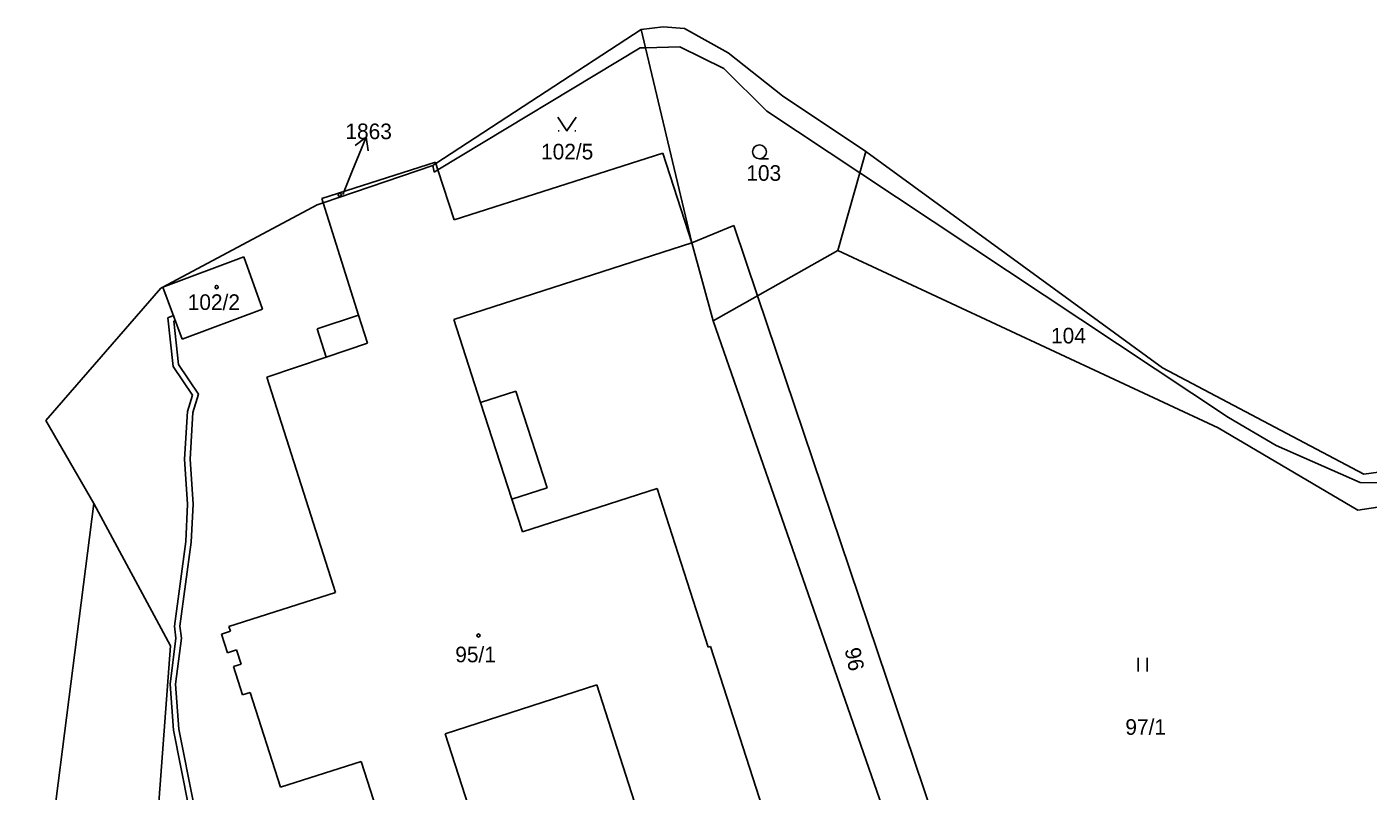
# Model space of a CAD drawing. Extents: x -670359 to -660124, y -978807 to -970072.
# Drawn here: x -670303.1 to -670157, y -977284.7 to -977201.4 of the extents above; entities that cross this region are included whole.
import ezdxf

# ---------------------------------------------------------------- set-up
doc = ezdxf.new("R2010")
doc.units = 0
for name, color, linetype in [('Hranice kat_území', 7, 'Continuous'), ('Hranice parcel', 7, 'Continuous'), ('Parcelní čísla', 7, 'Continuous'), ('Vnitřní kresba', 7, 'Continuous'), ('Věcná břemena k části', 7, 'Continuous'), ('Značky budov', 7, 'Continuous'), ('Značky kultur', 7, 'Continuous')]:
    doc.layers.add(name, color=color, linetype=linetype)

msp = doc.modelspace()

# ---------------------------------------------------------------- linework, layer by layer
at = {"layer": 'Hranice kat_území'}
for points in [[(-670236.21, -977201.71), (-670233.81, -977201.41)], [(-670233.81, -977201.41), (-670231.49, -977201.59)], [(-670236.21, -977201.71), (-670258.55, -977216.29)], [(-670231.49, -977201.59), (-670226.71, -977204.26)], [(-670226.71, -977204.26), (-670220.82, -977208.94)], [(-670220.82, -977208.94), (-670211.74, -977215)], [(-670270.98, -977220.13), (-670258.59, -977216.15)], [(-670258.59, -977216.15), (-670258.55, -977216.29)], [(-670211.74, -977215), (-670179.42, -977238.58)], [(-670270.83, -977220.6), (-670270.98, -977220.13)], [(-670288.28, -977229.78), (-670271.48, -977220.82)], [(-670271.48, -977220.82), (-670270.83, -977220.6)], [(-670301.02, -977244.29), (-670288.51, -977229.9)], [(-670288.51, -977229.9), (-670288.28, -977229.78)], [(-670179.42, -977238.58), (-670157.5, -977250.17)], [(-670295.8, -977253.36), (-670301.02, -977244.29)], [(-670157.5, -977250.17), (-670145.24, -977248.5)], [(-670303.09, -977310.58), (-670295.8, -977253.36)]]:
    msp.add_lwpolyline(points, dxfattribs=at)
at = {"layer": 'Hranice parcel'}
for q in [(-670270.83, -977220.6), (-670258.55, -977216.29)]:
    msp.add_line((-670258.89, -977216.51), q, dxfattribs=at)
for points in [[(-670235.74, -977203.69), (-670236.21, -977201.71)], [(-670230.7, -977224.96), (-670235.74, -977203.69)], [(-670256.57, -977222.45), (-670233.85, -977215.16)], [(-670233.85, -977215.16), (-670230.7, -977224.96)], [(-670212.4, -977217.33), (-670211.74, -977215)], [(-670258.55, -977216.29), (-670258.33, -977216.99)], [(-670258.33, -977216.99), (-670256.57, -977222.45)], [(-670214.78, -977225.78), (-670212.4, -977217.33)], [(-670266.96, -977232.82), (-670270.83, -977220.6)], [(-670230.7, -977224.96), (-670256.6, -977233.31)], [(-670230.7, -977224.96), (-670228.36, -977233.44)], [(-670214.78, -977225.78), (-670223.53, -977230.71)], [(-670173.39, -977245.1), (-670214.78, -977225.78)], [(-670288.28, -977229.78), (-670279.45, -977226.47)], [(-670279.45, -977226.47), (-670277.44, -977232.19)], [(-670288.28, -977229.78), (-670286.18, -977235.45)], [(-670228.36, -977233.44), (-670223.53, -977230.71)], [(-670192.35, -977323.19), (-670223.53, -977230.71)], [(-670286.18, -977235.45), (-670277.44, -977232.19)], [(-670266.96, -977232.82), (-670271.46, -977234.32)], [(-670253.68, -977242.35), (-670256.6, -977233.31)], [(-670196.76, -977324.36), (-670228.36, -977233.44)], [(-670271.46, -977234.32), (-670270.48, -977237.41)], [(-670276.94, -977239.59), (-670270.48, -977237.41)], [(-670276.94, -977239.59), (-670269.49, -977263.05)], [(-670249.86, -977241.11), (-670253.68, -977242.35)], [(-670246.43, -977251.65), (-670249.86, -977241.11)], [(-670158.17, -977254.09), (-670173.39, -977245.1)], [(-670250.27, -977252.89), (-670246.43, -977251.65)], [(-670234.44, -977251.73), (-670249.12, -977256.45)], [(-670228.89, -977268.99), (-670234.44, -977251.73)], [(-670249.12, -977256.45), (-670250.27, -977252.89)], [(-670151.87, -977253.14), (-670158.17, -977254.09)], [(-670269.49, -977263.05), (-670281.1, -977266.74)], [(-670280.93, -977267.27), (-670281.88, -977267.58)], [(-670281.1, -977266.74), (-670280.93, -977267.27)], [(-670281.88, -977267.58), (-670281.23, -977269.62)], [(-670281.23, -977269.62), (-670280.27, -977269.31)], [(-670280.27, -977269.31), (-670279.77, -977270.85)], [(-670228.65, -977268.92), (-670228.89, -977268.99)], [(-670215.56, -977309.6), (-670228.65, -977268.92)], [(-670279.77, -977270.85), (-670280.57, -977271.11)], [(-670280.57, -977271.11), (-670279.59, -977274.19)], [(-670257.55, -977278.44), (-670241.01, -977273.11)], [(-670241.01, -977273.11), (-670231.87, -977301.63)], [(-670279.59, -977274.19), (-670278.79, -977273.93)], [(-670278.79, -977273.93), (-670275.47, -977284.26)], [(-670240.8, -977330.34), (-670257.55, -977278.44)], [(-670275.47, -977284.26), (-670266.7, -977281.45)], [(-670266.7, -977281.45), (-670263.03, -977292.85)]]:
    msp.add_lwpolyline(points, dxfattribs=at)
at = {"layer": 'Parcelní čísla'}
for p, q in [((-670267.33, -977214.35), (-670266.15, -977213.42)), ((-670268.68, -977219.67), (-670267.65, -977217.13))]:
    msp.add_line(p, q, dxfattribs=at)
msp.add_lwpolyline([(-670267.65, -977217.13), (-670266.15, -977213.42), (-670265.94, -977214.91)], dxfattribs=at)
at = {"layer": 'Vnitřní kresba'}
for points in [[(-670236.31, -977203.71), (-670258.33, -977216.99)], [(-670235.74, -977203.69), (-670236.31, -977203.71)], [(-670231.98, -977203.58), (-670235.74, -977203.69)], [(-670227.2, -977205.94), (-670231.98, -977203.58)], [(-670222.51, -977210.61), (-670227.2, -977205.94)], [(-670212.4, -977217.33), (-670222.51, -977210.61)], [(-670258.89, -977216.51), (-670258.73, -977217.23)], [(-670258.33, -977216.99), (-670258.73, -977217.23)], [(-670172.26, -977243.99), (-670212.4, -977217.33)], [(-670226.12, -977223.06), (-670230.7, -977224.96)], [(-670223.53, -977230.71), (-670226.12, -977223.06)], [(-670265.99, -977235.89), (-670266.96, -977232.82)], [(-670270.48, -977237.41), (-670265.99, -977235.89)], [(-670253.68, -977242.35), (-670250.27, -977252.89)], [(-670167.04, -977247.04), (-670172.26, -977243.99)], [(-670157.9, -977251.05), (-670167.04, -977247.04)], [(-670152.1, -977251.15), (-670157.9, -977251.05)], [(-670295.8, -977253.36), (-670287.45, -977268.85)], [(-670287.45, -977268.85), (-670289.49, -977296.13)]]:
    msp.add_lwpolyline(points, dxfattribs=at)
at = {"layer": 'Věcná břemena k části'}
for points in [[(-670287.74, -977233.12), (-670287.13, -977232.88)], [(-670287.15, -977238.41), (-670287.74, -977233.12)], [(-670287.13, -977232.88), (-670286.93, -977233.42)], [(-670286.93, -977233.42), (-670287.1, -977233.49)], [(-670287.1, -977233.49), (-670286.57, -977238.19)], [(-670285.05, -977241.53), (-670287.15, -977238.41)], [(-670286.57, -977238.19), (-670284.39, -977241.43)], [(-670285.61, -977243.33), (-670285.05, -977241.53)], [(-670284.39, -977241.43), (-670285.01, -977243.43)], [(-670285.91, -977248.51), (-670285.61, -977243.33)], [(-670285.01, -977243.43), (-670285.31, -977248.51)], [(-670285.58, -977253.41), (-670285.91, -977248.51)], [(-670285.31, -977248.51), (-670284.98, -977253.41)], [(-670285.79, -977257.5), (-670285.58, -977253.41)], [(-670284.98, -977253.41), (-670285.19, -977257.56)], [(-670287.02, -977266.7), (-670285.79, -977257.5)], [(-670285.19, -977257.56), (-670286.42, -977266.7)], [(-670286.85, -977268.01), (-670287.02, -977266.7)], [(-670286.42, -977266.7), (-670286.25, -977268.01)], [(-670287.5, -977273.02), (-670286.85, -977268.01)], [(-670286.25, -977268.01), (-670286.9, -977273.04)], [(-670287.13, -977278.03), (-670287.5, -977273.02)], [(-670286.9, -977273.04), (-670286.53, -977277.95)], [(-670285.47, -977286.29), (-670287.13, -977278.03)], [(-670286.53, -977277.95), (-670284.89, -977286.15)]]:
    msp.add_lwpolyline(points, dxfattribs=at)
at = {"layer": 'Značky budov'}
for centre in [(-670282.42, -977229.77), (-670253.91, -977267.73)]:
    msp.add_circle(centre, 0.175, dxfattribs=at)
at = {"layer": 'Značky kultur'}
for p, q in [((-670245.23, -977212.75), (-670245.13, -977212.75)), ((-670243.43, -977212.75), (-670243.33, -977212.75)), ((-670223.32, -977215.78), (-670222.32, -977215.78)), ((-670182.09, -977270.17), (-670182.09, -977271.67)), ((-670181.09, -977271.67), (-670181.09, -977270.17))]:
    msp.add_line(p, q, dxfattribs=at)
msp.add_lwpolyline([(-670245.28, -977211.25), (-670244.28, -977212.75), (-670243.28, -977211.25)], dxfattribs=at)
for centre, radius in [((-670223.32, -977215.03), 0.75), ((-670269.02, -977219.72), 0.175), ((-670282.42, -977229.77), 0.175), ((-670253.91, -977267.73), 0.175)]:
    msp.add_circle(centre, radius, dxfattribs=at)

# ---------------------------------------------------------------- texts
at = {"layer": 'Parcelní čísla'}
for s, height, p in [('1863', 1.7, (-670268.4, -977213.65)), ('102/5', 1.7, (-670247.1, -977215.86)), ('103', 1.7, (-670224.75, -977218.19)), ('1863', 0.1, (-670268.83, -977219.67)), ('102/2', 1.7, (-670285.57, -977232.26)), ('104', 1.7, (-670191.57, -977235.91)), ('95/1', 1.7, (-670256.44, -977270.65)), ('97/1', 1.7, (-670183.48, -977278.55))]:
    msp.add_text(s, height=height, dxfattribs=at).set_placement(p)
msp.add_text('96', height=1.7, rotation=281.7418, dxfattribs=at).set_placement((-670214.05, -977269.24))

doc.saveas('drawing.dxf')
